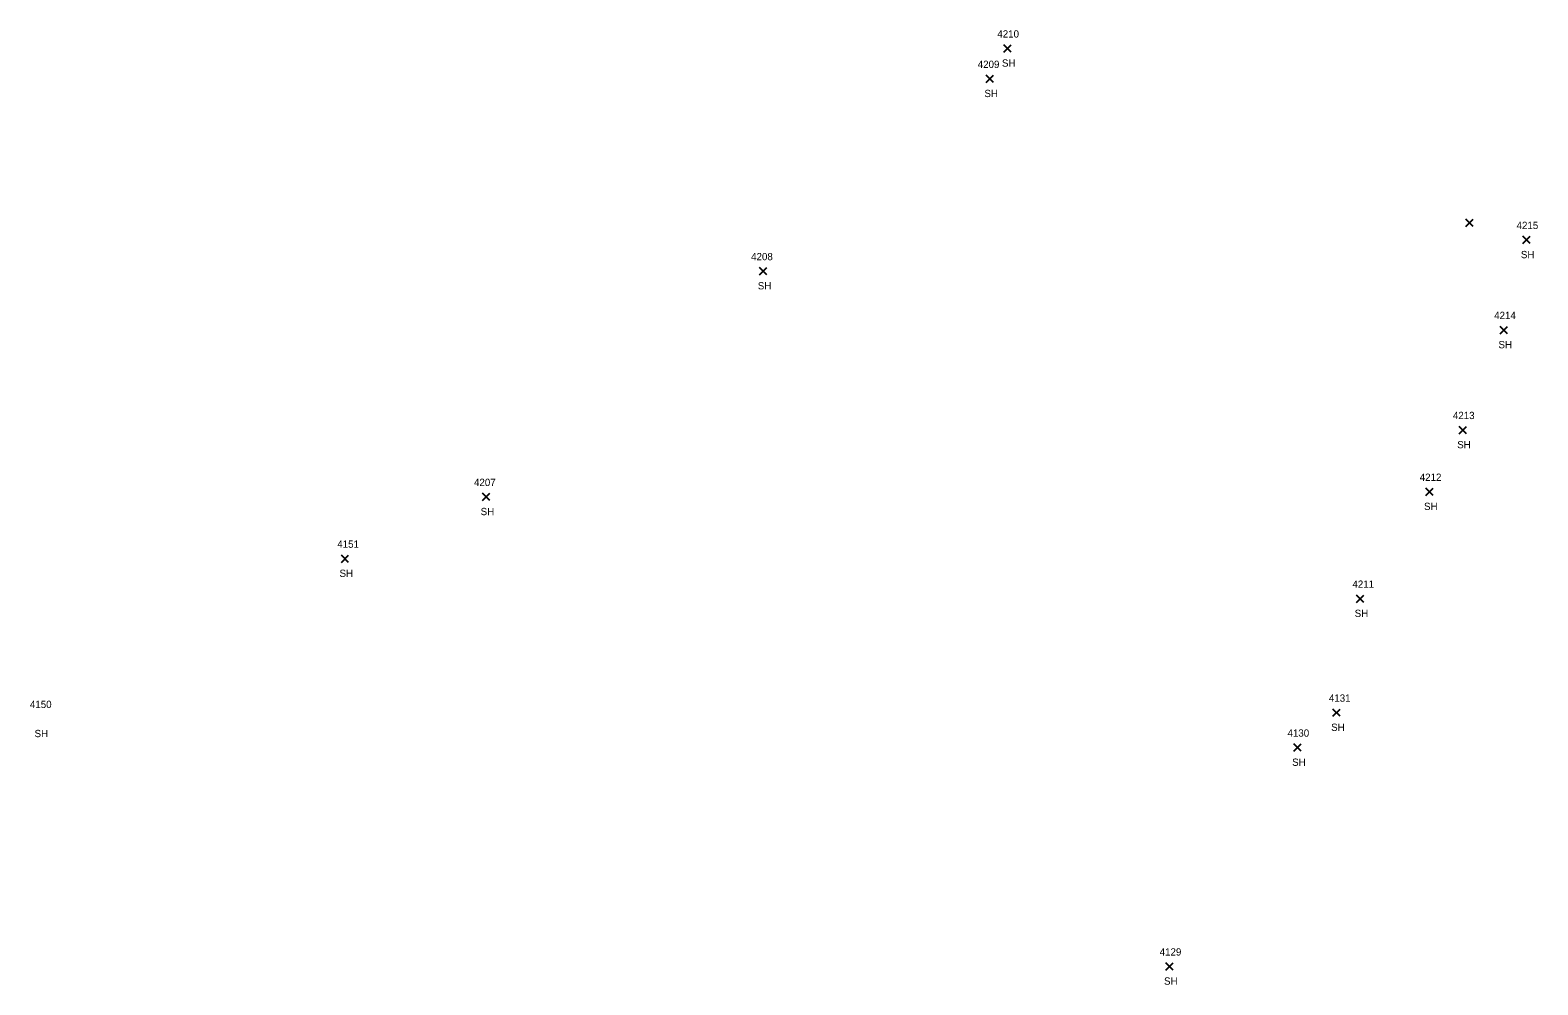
# Model space of a CAD drawing. Extents: x 1601151 to 1602912, y 499508 to 501770.
# Drawn here: x 1602498.4 to 1602912, y 500001.3 to 500263.3 of the extents above; entities that cross this region are included whole.
import ezdxf

# ---------------------------------------------------------------- set-up
doc = ezdxf.new("R2010")
doc.units = 0
for name, color, linetype in [('L_A', 7, 'Continuous'), ('L_I', 7, 'Continuous'), ('L_TIC', 7, 'Continuous')]:
    doc.layers.add(name, color=color, linetype=linetype)

msp = doc.modelspace()

# ---------------------------------------------------------------- linework, layer by layer
at = {"layer": 'L_TIC'}
for points in [[(1602765.52, 500257.26), (1602767.52, 500259.26)], [(1602767.52, 500257.26), (1602765.52, 500259.26)], [(1602760.7, 500248.92), (1602762.7, 500250.92)], [(1602762.7, 500248.92), (1602760.7, 500250.92)], [(1602892.27, 500209.44), (1602894.27, 500211.44)], [(1602894.27, 500209.44), (1602892.27, 500211.44)], [(1602907.89, 500204.72), (1602909.89, 500206.72)], [(1602909.89, 500204.72), (1602907.89, 500206.72)], [(1602698.53, 500196.16), (1602700.53, 500198.16)], [(1602700.53, 500196.16), (1602698.53, 500198.16)], [(1602901.74, 500180.01), (1602903.74, 500182.01)], [(1602903.74, 500180.01), (1602901.74, 500182.01)], [(1602890.42, 500152.57), (1602892.42, 500154.57)], [(1602892.42, 500152.57), (1602890.42, 500154.57)], [(1602881.32, 500135.62), (1602883.32, 500137.62)], [(1602883.32, 500135.62), (1602881.32, 500137.62)], [(1602622.5, 500134.21), (1602624.5, 500136.21)], [(1602624.5, 500134.21), (1602622.5, 500136.21)], [(1602583.77, 500117.26), (1602585.77, 500119.26)], [(1602585.77, 500117.26), (1602583.77, 500119.26)], [(1602862.29, 500106.28), (1602864.29, 500108.28)], [(1602864.29, 500106.28), (1602862.29, 500108.28)], [(1602855.83, 500075.02), (1602857.83, 500077.02)], [(1602857.83, 500075.02), (1602855.83, 500077.02)], [(1602845.13, 500065.43), (1602847.13, 500067.43)], [(1602847.13, 500065.43), (1602845.13, 500067.43)], [(1602809.98, 500005.37), (1602811.98, 500007.37)], [(1602811.98, 500005.37), (1602809.98, 500007.37)]]:
    msp.add_lwpolyline(points, dxfattribs=at)

# ---------------------------------------------------------------- texts
at = {"layer": 'L_A'}
for p in [(1602765.01, 500253.26), (1602760.19, 500244.92), (1602907.38, 500200.72), (1602698.02, 500192.16), (1602901.23, 500176.01), (1602889.91, 500148.57), (1602880.81, 500131.62), (1602621.99, 500130.21), (1602583.26, 500113.26), (1602861.78, 500102.28), (1602499.59, 500069.3), (1602855.32, 500071.02), (1602844.62, 500061.43), (1602809.47, 500001.37)]:
    msp.add_text('SH', height=2, dxfattribs=at).set_placement(p)
at = {"layer": 'L_I'}
for s, p in [('4210', (1602763.74, 500261.26)), ('4209', (1602758.36, 500252.92)), ('4215', (1602906.2, 500208.72)), ('4208', (1602696.19, 500200.16)), ('4214', (1602900.05, 500184.01)), ('4213', (1602888.73, 500156.57)), ('4212', (1602879.63, 500139.62)), ('4207', (1602620.16, 500138.21)), ('4151', (1602582.65, 500121.26)), ('4211', (1602861.16, 500110.28)), ('4131', (1602854.71, 500079.02)), ('4150', (1602498.32, 500077.3)), ('4130', (1602843.35, 500069.43)), ('4129', (1602808.28, 500009.37))]:
    msp.add_text(s, height=2, dxfattribs=at).set_placement(p)

doc.saveas('drawing.dxf')
